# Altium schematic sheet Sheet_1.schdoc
size 317 x 205 mm
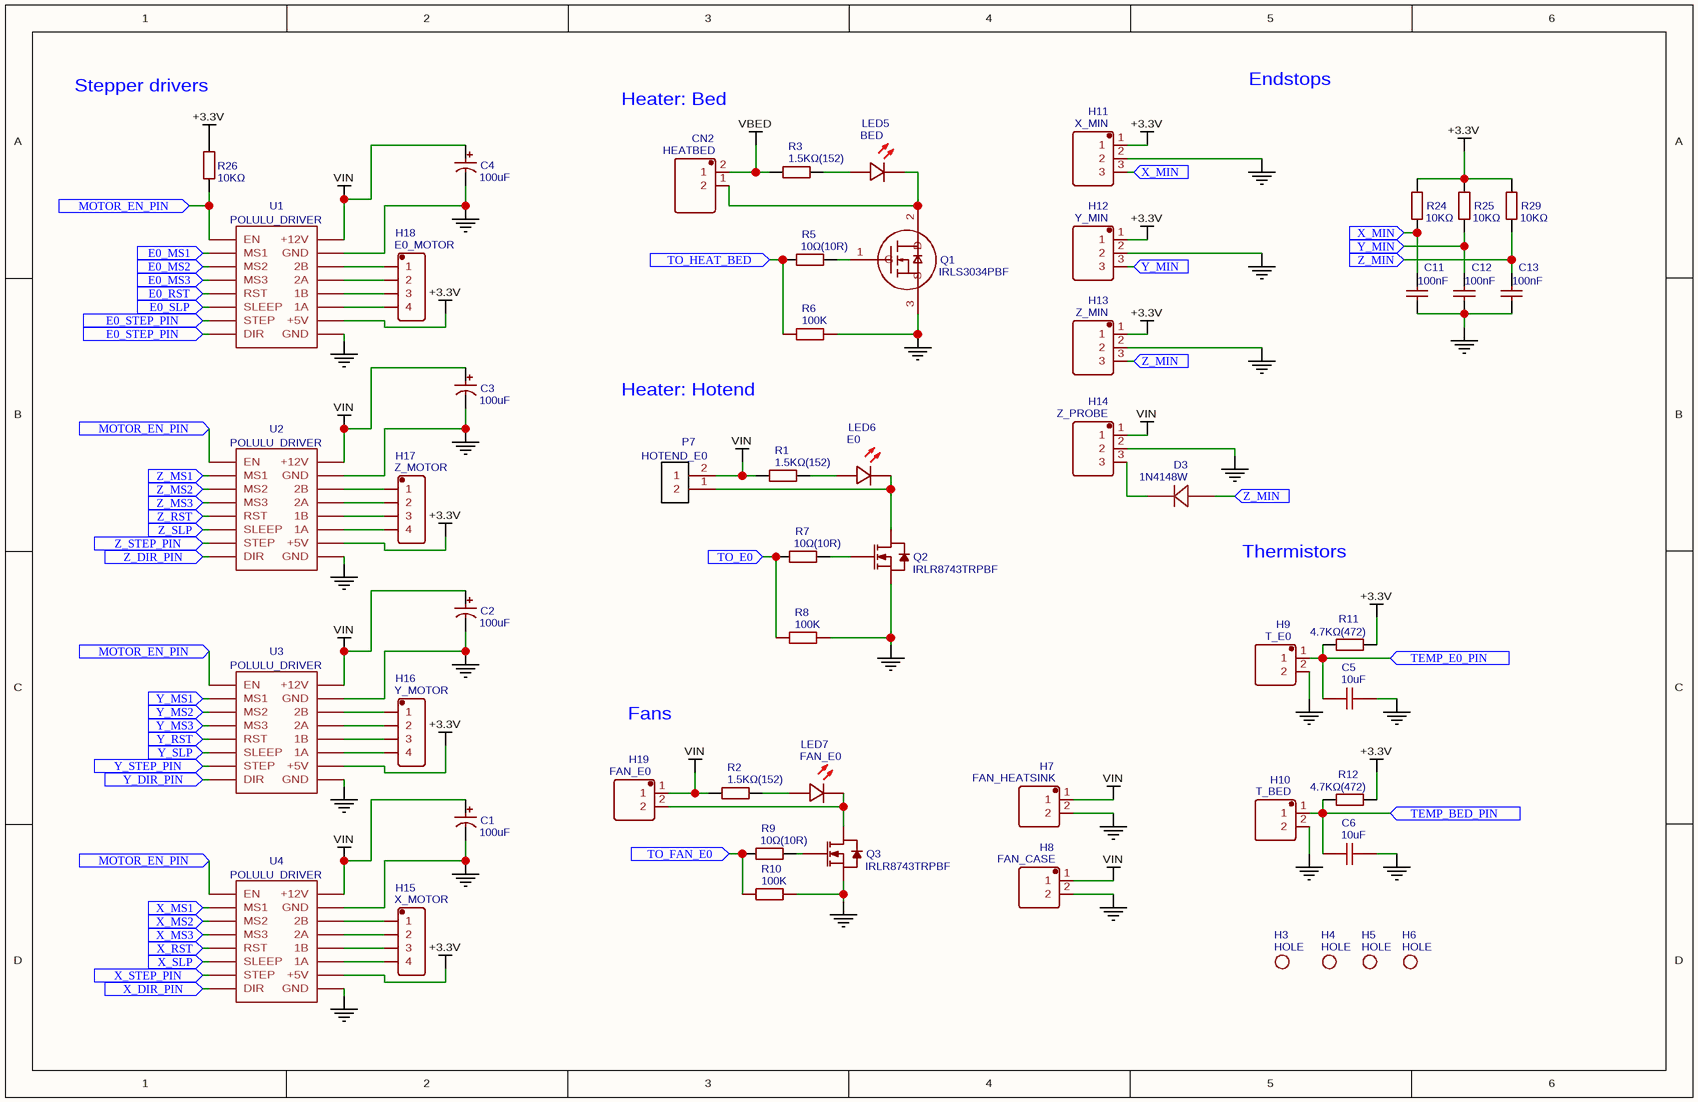
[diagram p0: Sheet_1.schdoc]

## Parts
C1  100uF  [CAP-D6.3XH7.7]
C2  100uF  [CAP-D6.3XH7.7]
C3  100uF  [CAP-D6.3XH7.7]
C4  100uF  [CAP-D6.3XH7.7]
C5  10uF  [0805]
C6  10uF  [0805]
C11  100nF  [0805]
C12  100nF  [0805]
C13  100nF  [0805]
CN2  HEATBED  [MKDS3/2-5.08]
D3  1N4148W  [SOD-123FL]
H3  HOLE  [HOLE_3MM5]
H4  HOLE  [HOLE_3MM5]
H5  HOLE  [HOLE_3MM5]
H6  HOLE  [HOLE_3MM5]
H7  FAN_HEATSINK  [210S-1X2P]
H8  FAN_CASE  [210S-1X2P]
H9  T_E0  [210S-1X2P]
H10  T_BED  [210S-1X2P]
H11  X_MIN  [210S-1X3P]
H12  Y_MIN  [210S-1X3P]
H13  Z_MIN  [210S-1X3P]
H14  Z_PROBE  [210S-1X3P]
H15  X_MOTOR  [DIP-1X4P-2.54MM-M]
H16  Y_MOTOR  [DIP-1X4P-2.54MM-M]
H17  Z_MOTOR  [DIP-1X4P-2.54MM-M]
H18  E0_MOTOR  [DIP-1X4P-2.54MM-M]
H19  FAN_E0  [210S-1X2P]
LED5  BED  [LED-0805]
LED6  E0  [LED-0805]
LED7  FAN_E0  [LED-0805]
P7  HOTEND_E0  [WJ500V-5.08-2P]
Q1  IRLS3034PBF  [D2PAK]
Q2  IRLR8743TRPBF  [TO-252-2]
Q3  IRLR8743TRPBF  [TO-252-2]
R1  1.5KΩ(152)  [0805]
R2  1.5KΩ(152)  [0805]
R3  1.5KΩ(152)  [0805]
R5  10Ω(10R)  [0805]
R6  100K  [0805]
R7  10Ω(10R)  [0805]
R8  100K  [0805]
R9  10Ω(10R)  [0805]
R10  100K  [0805]
R11  4.7KΩ(472)  [0805]
R12  4.7KΩ(472)  [0805]
R24  10KΩ  [0805]
R25  10KΩ  [0805]
R26  10KΩ  [0805]
R29  10KΩ  [0805]
U1  POLULU_DRIVER  [POLULU_DRIVER]
U2  POLULU_DRIVER  [POLULU_DRIVER]
U3  POLULU_DRIVER  [POLULU_DRIVER]
U4  POLULU_DRIVER  [POLULU_DRIVER]

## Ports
E0_MS1, E0_MS2, E0_MS3, E0_RST, E0_SLP, E0_STEP_PIN, MOTOR_EN_PIN, TEMP_BED_PIN, TEMP_E0_PIN, TO_E0, TO_FAN_E0, TO_HEAT_BED, X_DIR_PIN, X_MIN, X_MS1, X_MS2, X_MS3, X_RST, X_SLP, X_STEP_PIN, Y_DIR_PIN, Y_MIN, Y_MS1, Y_MS2, Y_MS3, Y_RST, Y_SLP, Y_STEP_PIN, Z_DIR_PIN, Z_MIN, Z_MS1, Z_MS2, Z_MS3, Z_RST, Z_SLP, Z_STEP_PIN

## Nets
+3.3V: H11.1 H12.1 H13.1 R11.2 R12.2 R24.2 R25.2 R26.2 R29.2 U1.10(+5V) U2.10(+5V) U3.10(+5V) U4.10(+5V)
GND: C1.2 C2.2 C3.2 C4.2 C11.2 C12.2 C13.2 H7.2 H8.2 H9.2 H10.2 H11.2 H12.2 H13.2 H14.2 Q1.3(S) Q2.3(S) Q3.3(S) U1.9(GND) U1.15(GND) U2.9(GND) U2.15(GND) U3.9(GND) U3.15(GND) U4.9(GND) U4.15(GND)
VBED: CN2.2(1) R3.1
VIN: C1.1 C2.1 C3.1 C4.1 H7.1 H8.1 H14.1 H19.1 P7.2(1) R1.1 R2.1 U1.16(+12V) U2.16(+12V) U3.16(+12V) U4.16(+12V)
E0_MS1: U1.2(MS1) ; port E0_MS1
E0_MS2: U1.3(MS2) ; port E0_MS2
E0_MS3: U1.4(MS3) ; port E0_MS3
E0_RST: U1.5(RST) ; port E0_RST
E0_SLP: U1.6(SLEEP) ; port E0_SLP
E0_STEP_PIN: U1.7(STEP) U1.8(DIR) ; port E0_STEP_PIN
MOTOR_EN_PIN: R26.1 U1.1(EN) U2.1(EN) U3.1(EN) U4.1(EN) ; port MOTOR_EN_PIN
TEMP_BED_PIN: H10.1 R12.1 ; port TEMP_BED_PIN
TEMP_E0_PIN: H9.1 R11.1 ; port TEMP_E0_PIN
TO_E0: R7.1 ; port TO_E0
TO_FAN_E0: R9.1 ; port TO_FAN_E0
TO_HEAT_BED: R5.1 ; port TO_HEAT_BED
X_DIR_PIN: U4.8(DIR) ; port X_DIR_PIN
X_MIN: C11.1 H11.3 R24.1 ; port X_MIN
X_MS1: U4.2(MS1) ; port X_MS1
X_MS2: U4.3(MS2) ; port X_MS2
X_MS3: U4.4(MS3) ; port X_MS3
X_RST: U4.5(RST) ; port X_RST
X_SLP: U4.6(SLEEP) ; port X_SLP
X_STEP_PIN: U4.7(STEP) ; port X_STEP_PIN
Y_DIR_PIN: U3.8(DIR) ; port Y_DIR_PIN
Y_MIN: C12.1 H12.3 R25.1 ; port Y_MIN
Y_MS1: U3.2(MS1) ; port Y_MS1
Y_MS2: U3.3(MS2) ; port Y_MS2
Y_MS3: U3.4(MS3) ; port Y_MS3
Y_RST: U3.5(RST) ; port Y_RST
Y_SLP: U3.6(SLEEP) ; port Y_SLP
Y_STEP_PIN: U3.7(STEP) ; port Y_STEP_PIN
Z_DIR_PIN: U2.8(DIR) ; port Z_DIR_PIN
Z_MIN: C13.1 D3.2(A) H13.3 R29.1 ; port Z_MIN
Z_MS1: U2.2(MS1) ; port Z_MS1
Z_MS2: U2.3(MS2) ; port Z_MS2
Z_MS3: U2.4(MS3) ; port Z_MS3
Z_RST: U2.5(RST) ; port Z_RST
Z_SLP: U2.6(SLEEP) ; port Z_SLP
Z_STEP_PIN: U2.7(STEP) ; port Z_STEP_PIN
NetCN2_1: CN2.1(2) LED5.2(-) Q1.2(D)
NetD3_1: D3.1(C) H14.3
NetH15_1: H15.1 U4.14(2B)
NetH15_2: H15.2 U4.13(2A)
NetH15_3: H15.3 U4.12(1B)
NetH15_4: H15.4 U4.11(1A)
NetH16_1: H16.1 U3.14(2B)
NetH16_2: H16.2 U3.13(2A)
NetH16_3: H16.3 U3.12(1B)
NetH16_4: H16.4 U3.11(1A)
NetH17_1: H17.1 U2.14(2B)
NetH17_2: H17.2 U2.13(2A)
NetH17_3: H17.3 U2.12(1B)
NetH17_4: H17.4 U2.11(1A)
NetH18_1: H18.1 U1.14(2B)
NetH18_2: H18.2 U1.13(2A)
NetH18_3: H18.3 U1.12(1B)
NetH18_4: H18.4 U1.11(1A)
NetH19_2: H19.2 LED7.2(-) Q3.4(D)
NetLED5_1: LED5.1(+) R3.2
NetLED6_1: LED6.1(+) R1.2
NetLED6_2: LED6.2(-) P7.1(2) Q2.4(D)
NetLED7_1: LED7.1(+) R2.2
NetQ1_1: Q1.1(G) R5.2
NetQ2_1: Q2.1(G) R7.2
NetQ3_1: Q3.1(G) R9.2

Not connected (* = marked no-connect by the designer): C5 1 2; C6 1 2; R6 1 2; R8 1 2; R10 1 2

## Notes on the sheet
- Stepper drivers
- Heater: Bed
- Endstops
- Heater: Hotend
- Thermistors
- Fans

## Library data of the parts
C1-C4 = 100uF: BOM_Manufacturer: ROQANG; BOM_Manufacturer Part: RVT1V101M0607; nameAlias: Capacitance
C5 C6 = 10uF: BOM_Manufacturer: FH; BOM_Manufacturer Part: 0805B106K250NT; nameAlias: Capacitance
C11-C13 = 100nF: BOM_Manufacturer: YAGEO; BOM_Manufacturer Part: CC0805JRX7R9BB104; nameAlias: Capacitance
CN2 = HEATBED: BOM_Manufacturer: Phoenix Contact
D3 = 1N4148W: BOM_Manufacturer: Tak Cheong; Contributor: LCSC
H3-H6 = HOLE: Contributor: SparkFun
H7 = FAN_HEATSINK: BOM_Manufacturer: Ckmtw; BOM_Manufacturer Part: 210S-1*2P L=11.6MMGold-plated black; Contributor: LCSC
H8 = FAN_CASE: BOM_Manufacturer: Ckmtw; BOM_Manufacturer Part: 210S-1*2P L=11.6MMGold-plated black; Contributor: LCSC
H9 = T_E0: BOM_Manufacturer: Ckmtw; BOM_Manufacturer Part: 210S-1*2P L=11.6MMGold-plated black; Contributor: LCSC
H10 = T_BED: BOM_Manufacturer: Ckmtw; BOM_Manufacturer Part: 210S-1*2P L=11.6MMGold-plated black; Contributor: LCSC
H11 = X_MIN: BOM_Manufacturer: Ckmtw; BOM_Manufacturer Part: 210S-1*3P L=11.6MMGold-plated black; Contributor: LCSC
H12 = Y_MIN: BOM_Manufacturer: Ckmtw; BOM_Manufacturer Part: 210S-1*3P L=11.6MMGold-plated black; Contributor: LCSC
H13 = Z_MIN: BOM_Manufacturer: Ckmtw; BOM_Manufacturer Part: 210S-1*3P L=11.6MMGold-plated black; Contributor: LCSC
H14 = Z_PROBE: BOM_Manufacturer: Ckmtw; BOM_Manufacturer Part: 210S-1*3P L=11.6MMGold-plated black; Contributor: LCSC
H15 = X_MOTOR: BOM_Manufacturer: Ckmtw; BOM_Manufacturer Part: 210S-1*4P L=11.6MMGold-plated black; Contributor: LCSC
H16 = Y_MOTOR: BOM_Manufacturer: Ckmtw; BOM_Manufacturer Part: 210S-1*4P L=11.6MMGold-plated black; Contributor: LCSC
H17 = Z_MOTOR: BOM_Manufacturer: Ckmtw; BOM_Manufacturer Part: 210S-1*4P L=11.6MMGold-plated black; Contributor: LCSC
H18 = E0_MOTOR: BOM_Manufacturer: Ckmtw; BOM_Manufacturer Part: 210S-1*4P L=11.6MMGold-plated black; Contributor: LCSC
H19 = FAN_E0: BOM_Manufacturer: Ckmtw; BOM_Manufacturer Part: 210S-1*2P L=11.6MMGold-plated black; Contributor: LCSC
LED5 = BED: BOM_Manufacturer: Everlight Elec; BOM_Manufacturer Part: 17-21SURC/S530-A2/TR8
LED6 = E0: BOM_Manufacturer: Everlight Elec; BOM_Manufacturer Part: 17-21SURC/S530-A2/TR8
LED7 = FAN_E0: BOM_Manufacturer: Everlight Elec; BOM_Manufacturer Part: 17-21SURC/S530-A2/TR8
P7 = HOTEND_E0: BOM_Manufacturer: ReliaPro; BOM_Manufacturer Part: WJ500V-5.08-2P-14-00A
Q1 = IRLS3034PBF: BOM_Manufacturer: Infineon; Contributor: LCSC
Q2 Q3 = IRLR8743TRPBF: BOM_Manufacturer: IR
R1-R3 = 1.5KΩ(152): BOM_Manufacturer: YAGEO; BOM_Manufacturer Part: RC0805JR-071K5L; nameAlias: Value
R5 R7 R9 = 10Ω(10R): BOM_Manufacturer: YAGEO; BOM_Manufacturer Part: RC0805JR-0710RL; nameAlias: Value
R6 R8 R10 = 100K: BOM_Manufacturer: YAGEO; BOM_Manufacturer Part: RC0805DR-07100KL; nameAlias: Resistance (Ohms); Contributor: LCSC
R11 R12 = 4.7KΩ(472): BOM_Manufacturer: YAGEO; BOM_Manufacturer Part: RC0805JR-074K7L; nameAlias: Value
R24-R26 R29 = 10KΩ: BOM_Manufacturer: YAGEO; BOM_Manufacturer Part: RC0805JR-0710KL; nameAlias: Value
U1-U4 = POLULU_DRIVER: sourceId: KGSeAWhDB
